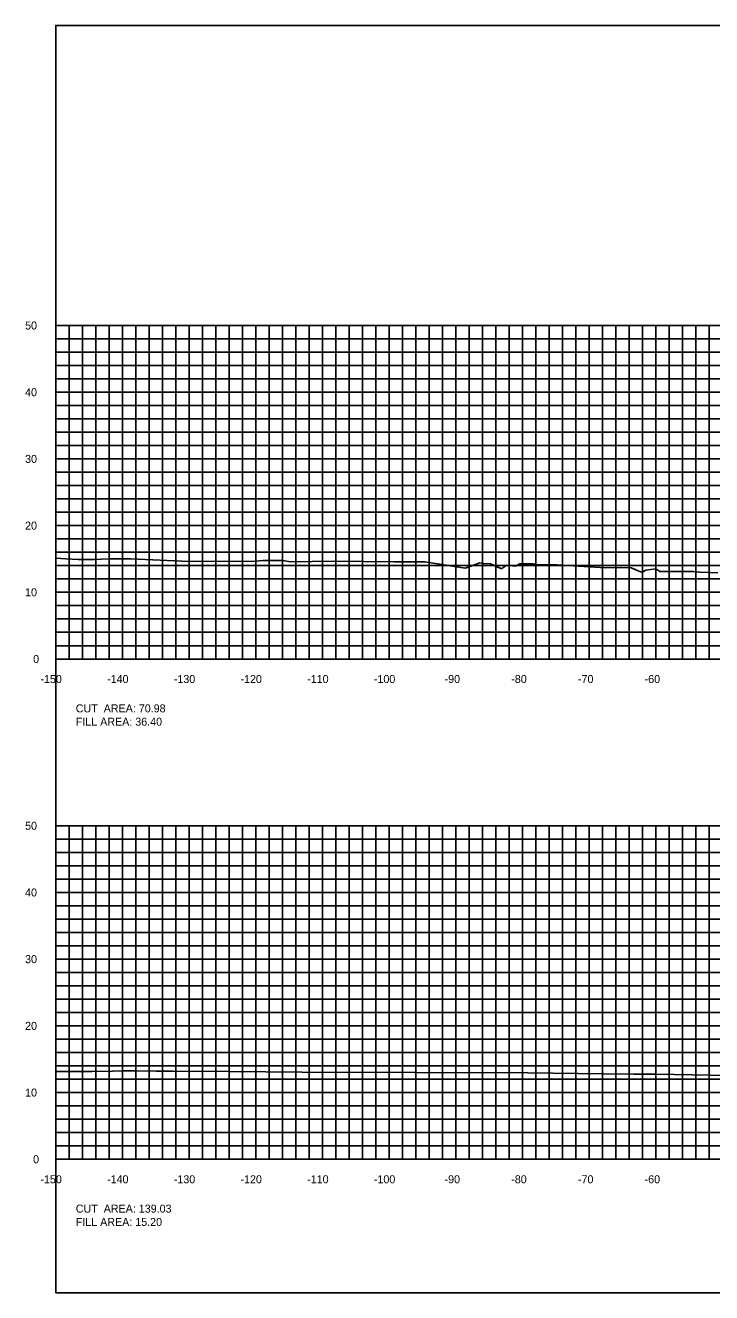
# Model space of a CAD drawing. Extents: x 1797714 to 1804825, y 249015 to 250269.
# Drawn here: x 1802136.4 to 1802239.4, y 250079.4 to 250269.4 of the extents above; entities that cross this region are included whole.
import ezdxf

# ---------------------------------------------------------------- set-up
doc = ezdxf.new("R2010")
doc.units = 0
for name, color, linetype in [('10', 7, 'Continuous'), ('31', 7, 'Continuous'), ('60', 7, 'Continuous'), ('ANNO-TXT', 7, 'Continuous'), ('Level 62', 7, 'Continuous'), ('M-ROADS', 7, 'Continuous')]:
    doc.layers.add(name, color=color, linetype=linetype)

msp = doc.modelspace()

# ---------------------------------------------------------------- linework, layer by layer
msp.add_lwpolyline([(1802141, 250079.43), (1802441, 250079.43), (1802441, 250269.43), (1802141, 250269.43)], close=True)
at = {"layer": '60'}
for p, q in [((1802140.94, 250224.43), (1802141, 250224.43)), ((1802141, 250174.43), (1802141, 250224.43)), ((1802140.94, 250214.43), (1802141, 250214.43)), ((1802140.94, 250204.43), (1802141, 250204.43)), ((1802140.94, 250194.43), (1802141, 250194.43)), ((1802140.94, 250184.43), (1802141, 250184.43)), ((1802140.94, 250174.43), (1802141, 250174.43)), ((1802141, 250174.43), (1802441, 250174.43)), ((1802141, 250174.37), (1802141, 250174.43)), ((1802151, 250174.37), (1802151, 250174.43)), ((1802161, 250174.37), (1802161, 250174.43)), ((1802171, 250174.37), (1802171, 250174.43)), ((1802181, 250174.37), (1802181, 250174.43)), ((1802191, 250174.37), (1802191, 250174.43)), ((1802201, 250174.37), (1802201, 250174.43)), ((1802211, 250174.37), (1802211, 250174.43)), ((1802221, 250174.37), (1802221, 250174.43)), ((1802231, 250174.37), (1802231, 250174.43)), ((1802140.94, 250149.43), (1802141, 250149.43)), ((1802141, 250099.43), (1802141, 250149.43)), ((1802140.94, 250139.43), (1802141, 250139.43)), ((1802140.94, 250129.43), (1802141, 250129.43)), ((1802140.94, 250119.43), (1802141, 250119.43)), ((1802140.94, 250109.43), (1802141, 250109.43)), ((1802140.94, 250099.43), (1802141, 250099.43)), ((1802141, 250099.43), (1802441, 250099.43)), ((1802141, 250099.37), (1802141, 250099.43)), ((1802151, 250099.37), (1802151, 250099.43)), ((1802161, 250099.37), (1802161, 250099.43)), ((1802171, 250099.37), (1802171, 250099.43)), ((1802181, 250099.37), (1802181, 250099.43)), ((1802191, 250099.37), (1802191, 250099.43)), ((1802201, 250099.37), (1802201, 250099.43)), ((1802211, 250099.37), (1802211, 250099.43)), ((1802221, 250099.37), (1802221, 250099.43)), ((1802231, 250099.37), (1802231, 250099.43))]:
    msp.add_line(p, q, dxfattribs=at)
at = {"layer": 'Level 62'}
for p, q in [((1802141, 250224.43), (1802441, 250224.43)), ((1802141, 250174.43), (1802141, 250224.43)), ((1802143, 250174.43), (1802143, 250224.43)), ((1802145, 250174.43), (1802145, 250224.43)), ((1802147, 250174.43), (1802147, 250224.43)), ((1802149, 250174.43), (1802149, 250224.43)), ((1802151, 250174.43), (1802151, 250224.43)), ((1802153, 250174.43), (1802153, 250224.43)), ((1802155, 250174.43), (1802155, 250224.43)), ((1802157, 250174.43), (1802157, 250224.43)), ((1802159, 250174.43), (1802159, 250224.43)), ((1802161, 250174.43), (1802161, 250224.43)), ((1802163, 250174.43), (1802163, 250224.43)), ((1802165, 250174.43), (1802165, 250224.43)), ((1802167, 250174.43), (1802167, 250224.43)), ((1802169, 250174.43), (1802169, 250224.43)), ((1802171, 250174.43), (1802171, 250224.43)), ((1802173, 250174.43), (1802173, 250224.43)), ((1802175, 250174.43), (1802175, 250224.43)), ((1802177, 250174.43), (1802177, 250224.43)), ((1802179, 250174.43), (1802179, 250224.43)), ((1802181, 250174.43), (1802181, 250224.43)), ((1802183, 250174.43), (1802183, 250224.43)), ((1802185, 250174.43), (1802185, 250224.43)), ((1802187, 250174.43), (1802187, 250224.43)), ((1802189, 250174.43), (1802189, 250224.43)), ((1802191, 250174.43), (1802191, 250224.43)), ((1802193, 250174.43), (1802193, 250224.43)), ((1802195, 250174.43), (1802195, 250224.43)), ((1802197, 250174.43), (1802197, 250224.43)), ((1802199, 250174.43), (1802199, 250224.43)), ((1802201, 250174.43), (1802201, 250224.43)), ((1802203, 250174.43), (1802203, 250224.43)), ((1802205, 250174.43), (1802205, 250224.43)), ((1802207, 250174.43), (1802207, 250224.43)), ((1802209, 250174.43), (1802209, 250224.43)), ((1802211, 250174.43), (1802211, 250224.43)), ((1802213, 250174.43), (1802213, 250224.43)), ((1802215, 250174.43), (1802215, 250224.43)), ((1802217, 250174.43), (1802217, 250224.43)), ((1802219, 250174.43), (1802219, 250224.43)), ((1802221, 250174.43), (1802221, 250224.43)), ((1802223, 250174.43), (1802223, 250224.43)), ((1802225, 250174.43), (1802225, 250224.43)), ((1802227, 250174.43), (1802227, 250224.43)), ((1802229, 250174.43), (1802229, 250224.43)), ((1802231, 250174.43), (1802231, 250224.43)), ((1802233, 250174.43), (1802233, 250224.43)), ((1802235, 250174.43), (1802235, 250224.43)), ((1802237, 250174.43), (1802237, 250224.43)), ((1802239, 250174.43), (1802239, 250224.43)), ((1802141, 250222.43), (1802441, 250222.43)), ((1802141, 250220.43), (1802441, 250220.43)), ((1802141, 250218.43), (1802441, 250218.43)), ((1802141, 250216.43), (1802441, 250216.43)), ((1802141, 250214.43), (1802441, 250214.43)), ((1802141, 250212.43), (1802441, 250212.43)), ((1802141, 250210.43), (1802441, 250210.43)), ((1802141, 250208.43), (1802441, 250208.43)), ((1802141, 250206.43), (1802441, 250206.43)), ((1802141, 250204.43), (1802441, 250204.43)), ((1802141, 250202.43), (1802441, 250202.43)), ((1802141, 250200.43), (1802441, 250200.43)), ((1802141, 250198.43), (1802441, 250198.43)), ((1802141, 250196.43), (1802441, 250196.43)), ((1802141, 250194.43), (1802441, 250194.43)), ((1802141, 250192.43), (1802441, 250192.43)), ((1802141, 250190.43), (1802441, 250190.43)), ((1802141, 250188.43), (1802441, 250188.43)), ((1802141, 250186.43), (1802441, 250186.43)), ((1802141, 250184.43), (1802441, 250184.43)), ((1802141, 250182.43), (1802441, 250182.43)), ((1802141, 250180.43), (1802441, 250180.43)), ((1802141, 250178.43), (1802441, 250178.43)), ((1802141, 250176.43), (1802441, 250176.43)), ((1802141, 250174.43), (1802441, 250174.43)), ((1802141, 250149.43), (1802441, 250149.43)), ((1802141, 250099.43), (1802141, 250149.43)), ((1802143, 250099.43), (1802143, 250149.43)), ((1802145, 250099.43), (1802145, 250149.43)), ((1802147, 250099.43), (1802147, 250149.43)), ((1802149, 250099.43), (1802149, 250149.43)), ((1802151, 250099.43), (1802151, 250149.43)), ((1802153, 250099.43), (1802153, 250149.43)), ((1802155, 250099.43), (1802155, 250149.43)), ((1802157, 250099.43), (1802157, 250149.43)), ((1802159, 250099.43), (1802159, 250149.43)), ((1802161, 250099.43), (1802161, 250149.43)), ((1802163, 250099.43), (1802163, 250149.43)), ((1802165, 250099.43), (1802165, 250149.43)), ((1802167, 250099.43), (1802167, 250149.43)), ((1802169, 250099.43), (1802169, 250149.43)), ((1802171, 250099.43), (1802171, 250149.43)), ((1802173, 250099.43), (1802173, 250149.43)), ((1802175, 250099.43), (1802175, 250149.43)), ((1802177, 250099.43), (1802177, 250149.43)), ((1802179, 250099.43), (1802179, 250149.43)), ((1802181, 250099.43), (1802181, 250149.43)), ((1802183, 250099.43), (1802183, 250149.43)), ((1802185, 250099.43), (1802185, 250149.43)), ((1802187, 250099.43), (1802187, 250149.43)), ((1802189, 250099.43), (1802189, 250149.43)), ((1802191, 250099.43), (1802191, 250149.43)), ((1802193, 250099.43), (1802193, 250149.43)), ((1802195, 250099.43), (1802195, 250149.43)), ((1802197, 250099.43), (1802197, 250149.43)), ((1802199, 250099.43), (1802199, 250149.43)), ((1802201, 250099.43), (1802201, 250149.43)), ((1802203, 250099.43), (1802203, 250149.43)), ((1802205, 250099.43), (1802205, 250149.43)), ((1802207, 250099.43), (1802207, 250149.43)), ((1802209, 250099.43), (1802209, 250149.43)), ((1802211, 250099.43), (1802211, 250149.43)), ((1802213, 250099.43), (1802213, 250149.43)), ((1802215, 250099.43), (1802215, 250149.43)), ((1802217, 250099.43), (1802217, 250149.43)), ((1802219, 250099.43), (1802219, 250149.43)), ((1802221, 250099.43), (1802221, 250149.43)), ((1802223, 250099.43), (1802223, 250149.43)), ((1802225, 250099.43), (1802225, 250149.43)), ((1802227, 250099.43), (1802227, 250149.43)), ((1802229, 250099.43), (1802229, 250149.43)), ((1802231, 250099.43), (1802231, 250149.43)), ((1802233, 250099.43), (1802233, 250149.43)), ((1802235, 250099.43), (1802235, 250149.43)), ((1802237, 250099.43), (1802237, 250149.43)), ((1802239, 250099.43), (1802239, 250149.43)), ((1802141, 250147.43), (1802441, 250147.43)), ((1802141, 250145.43), (1802441, 250145.43)), ((1802141, 250143.43), (1802441, 250143.43)), ((1802141, 250141.43), (1802441, 250141.43)), ((1802141, 250139.43), (1802441, 250139.43)), ((1802141, 250137.43), (1802441, 250137.43)), ((1802141, 250135.43), (1802441, 250135.43)), ((1802141, 250133.43), (1802441, 250133.43)), ((1802141, 250131.43), (1802441, 250131.43)), ((1802141, 250129.43), (1802441, 250129.43)), ((1802141, 250127.43), (1802441, 250127.43)), ((1802141, 250125.43), (1802441, 250125.43)), ((1802141, 250123.43), (1802441, 250123.43)), ((1802141, 250121.43), (1802441, 250121.43)), ((1802141, 250119.43), (1802441, 250119.43)), ((1802141, 250117.43), (1802441, 250117.43)), ((1802141, 250115.43), (1802441, 250115.43)), ((1802141, 250113.43), (1802441, 250113.43)), ((1802141, 250111.43), (1802441, 250111.43)), ((1802141, 250109.43), (1802441, 250109.43)), ((1802141, 250107.43), (1802441, 250107.43)), ((1802141, 250105.43), (1802441, 250105.43)), ((1802141, 250103.43), (1802441, 250103.43)), ((1802141, 250101.43), (1802441, 250101.43)), ((1802141, 250099.43), (1802441, 250099.43))]:
    msp.add_line(p, q, dxfattribs=at)
at = {"layer": 'M-ROADS'}
for points in [[(1802141, 250189.55), (1802142.49, 250189.46), (1802144.37, 250189.35), (1802146.75, 250189.35), (1802148.98, 250189.43), (1802152.24, 250189.47), (1802161, 250189.04), (1802170.9, 250189.11), (1802172.03, 250189.2), (1802173.76, 250189.2), (1802175.06, 250189.2), (1802176.22, 250188.98), (1802182.7, 250189.12), (1802191.75, 250189.02), (1802192.82, 250189), (1802193.72, 250189), (1802194.91, 250189), (1802196.35, 250189.02), (1802202.4, 250188.06), (1802202.52, 250188.09), (1802204.59, 250188.84), (1802205.14, 250188.77), (1802206.18, 250188.71), (1802207.72, 250188.01), (1802207.95, 250187.98), (1802208.02, 250188.09), (1802208.65, 250188.48), (1802209.91, 250188.35), (1802210.59, 250188.71), (1802210.64, 250188.7), (1802210.78, 250188.71), (1802212.55, 250188.69), (1802213.37, 250188.54), (1802215.85, 250188.54), (1802215.93, 250188.54), (1802216.17, 250188.54), (1802223.45, 250188.09), (1802225.87, 250188.16), (1802227.26, 250188.09), (1802228.7, 250187.5), (1802229.02, 250187.48), (1802229.47, 250187.75), (1802230.97, 250187.94), (1802231.6, 250187.54), (1802232.95, 250187.56), (1802236.6, 250187.53), (1802237.6, 250187.47), (1802240.3, 250187.34)], [(1802141, 250112.61), (1802146.4, 250112.61), (1802149.51, 250112.63), (1802151.03, 250112.69), (1802152.45, 250112.67), (1802152.86, 250112.68), (1802153, 250112.68), (1802153.07, 250112.67), (1802156.09, 250112.65), (1802158.57, 250112.65), (1802167.04, 250112.61), (1802177.91, 250112.49), (1802211.78, 250112.38), (1802223.11, 250112.24), (1802227.69, 250112.18), (1802231.03, 250112.21), (1802239.17, 250112.03), (1802243.28, 250111.98)]]:
    msp.add_lwpolyline(points, dxfattribs=at)

# ---------------------------------------------------------------- texts
at = {"layer": '10'}
for s, p in [('-150', (1802138.7, 250170.83)), ('-140', (1802148.7, 250170.83)), ('-130', (1802158.7, 250170.83)), ('-120', (1802168.7, 250170.83)), ('-110', (1802178.7, 250170.83)), ('-100', (1802188.7, 250170.83)), ('-90', (1802199.3, 250170.83)), ('-80', (1802209.3, 250170.83)), ('-70', (1802219.3, 250170.83)), ('-60', (1802229.3, 250170.83)), ('-150', (1802138.7, 250095.83)), ('-140', (1802148.7, 250095.83)), ('-130', (1802158.7, 250095.83)), ('-120', (1802168.7, 250095.83)), ('-110', (1802178.7, 250095.83)), ('-100', (1802188.7, 250095.83)), ('-90', (1802199.3, 250095.83)), ('-80', (1802209.3, 250095.83)), ('-70', (1802219.3, 250095.83)), ('-60', (1802229.3, 250095.83))]:
    msp.add_text(s, height=1.2, dxfattribs=at).set_placement(p)
at = {"layer": '31'}
for s, p in [('50', (1802136.4, 250223.83)), ('40', (1802136.4, 250213.83)), ('30', (1802136.4, 250203.83)), ('20', (1802136.4, 250193.83)), ('10', (1802136.4, 250183.83)), ('0', (1802137.6, 250173.83)), ('50', (1802136.4, 250148.83)), ('40', (1802136.4, 250138.83)), ('30', (1802136.4, 250128.83)), ('20', (1802136.4, 250118.83)), ('10', (1802136.4, 250108.83)), ('0', (1802137.6, 250098.83))]:
    msp.add_text(s, height=1.2, dxfattribs=at).set_placement(p)
at = {"layer": '60'}
for p in [(1802141, 250174.43), (1802141, 250099.43)]:
    msp.add_text('-', height=0.0001, dxfattribs=at).set_placement(p)
at = {"layer": 'ANNO-TXT'}
for s, p in [('CUT  AREA: 70.98', (1802144, 250166.43)), ('FILL AREA: 36.40', (1802144, 250164.43)), ('CUT  AREA: 139.03', (1802144, 250091.43)), ('FILL AREA: 15.20', (1802144, 250089.43))]:
    msp.add_text(s, height=1.2, dxfattribs=at).set_placement(p)

doc.saveas('drawing.dxf')
